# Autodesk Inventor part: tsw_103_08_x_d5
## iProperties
Created: 2006-03
Part Number: tsw_103_08_x_d5
Document SubType Name: Modeling
Designer: Elise Moss
Author: Elise Moss
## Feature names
1. Base1
